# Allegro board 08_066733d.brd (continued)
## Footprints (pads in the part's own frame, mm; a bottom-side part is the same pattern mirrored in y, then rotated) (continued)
DFN2_1_6X1
  rect 0.508x0.787 smd: A(0.604,0) C(-0.604,0)
DFN10_3X3_PAD2_4X1_7
  oval 0.279x0.711 smd: 1(-1,-1.406) 2(-0.5,-1.406) 3(0,-1.406) 4(0.5,-1.406) 5(1,-1.406) 6(1,1.406) 7(0.5,1.406) 8(0,1.406) 9(-0.5,1.406) 10(-1,1.406)
  rect 2.388x1.702 smd: PAD(0,0)
F2606
  rect 1.651x1.651 smd: 1(-3.35,0) 3(3.35,0)
  rect 2.591x2.591 smd: 2(0,0)
L1206
  rect 1.524x1.575 smd: 1(-1.714,0) 2(1.714,0)
L1210H67
  rect 1.245x2.007 smd: 1(-1.272,0) 2(1.272,0)
LED0603-2
  rect 0.787x0.787 smd: A(0.787,0) C(-0.787,0)
LED0603_A
  rect 0.889x0.787 smd: A(0.845,0) C(-0.845,0)
LQFN20_4X3_PAD2_65X1_65
  rect 0.381x0.381 smd: (-1.809,1.31) (-1.809,-1.31) (1.809,1.31) (1.809,-1.31)
  oval 0.279x0.737 smd: 1(-1.25,-1.393) 2(-0.75,-1.393) 3(-0.25,-1.393) 4(0.25,-1.393) 5(0.75,-1.393) 6(1.25,-1.393) 11(1.25,1.393) 12(0.75,1.393) 13(0.25,1.393) 14(-0.25,1.393) 15(-0.75,1.393) 16(-1.25,1.393)
  oval 0.737x0.279 smd: 7(1.893,-0.75) 8(1.893,-0.25) 9(1.893,0.25) 10(1.893,0.75) 17(-1.893,0.75) 18(-1.893,0.25) 19(-1.893,-0.25) 20(-1.893,-0.75)
  rect 2.642x1.651 smd: PAD(0,0)
LSML208W216H122
  rect 1.168x4.394 smd: 1(-1.651,0) 2(1.651,0)
LSMSQ157H83_A
  rect 0.965x3.708 smd: 1(-1.181,0) 2(1.181,0)
LSMSQ157H122
  rect 0.965x3.708 smd: 1(-1.181,0) 2(1.181,0)
POWERFLAT_33X33
  rect 0.406x0.762 smd: 1(-0.975,-1.519) 2(-0.325,-1.519) 3(0.325,-1.519) 4(0.975,-1.519)
  round 0.127 smd: 5(0.975,1.519) 6(0.325,1.519) 7(-0.325,1.519)
  custom 0.597x0.597 smd: 8(-1.029,1.519)
QFN12_2X2_PAD0_7X0_7
  oval 0.279x0.711 smd: 1(-0.75,-0.906) 2(-0.25,-0.906) 3(0.25,-0.906) 4(0.75,-0.906) 7(0.75,0.906) 8(0.25,0.906) 9(-0.25,0.906) 10(-0.75,0.906)
  oval 0.711x0.279 smd: 5(0.906,-0.25) 6(0.906,0.25) 11(-0.906,0.25) 12(-0.906,-0.25)
  rect 0.711x0.711 smd: PAD(0,0)
QFN14_3_5X3_5_PAD2_05X2_05
  oval 0.889x0.305 smd: 1(-1.7,-0.75) 7(1.7,-0.75) 8(1.7,0.75) 14(-1.7,0.75)
  oval 0.305x0.889 smd: 2(-1,-1.7) 3(-0.5,-1.7) 4(0,-1.7) 5(0.5,-1.7) 6(1,-1.7) 9(1,1.7) 10(0.5,1.7) 11(0,1.7) 12(-0.5,1.7) 13(-1,1.7)
  rect 2.057x2.057 smd: PAD(0,0)
QFN18_3X3_PAD1_51X1_7
  oval 0.279x0.711 smd: 1(-1,-1.406) 2(-0.5,-1.406) 3(0,-1.406) 4(0.5,-1.406) 5(1,-1.406) 10(1,1.406) 11(0.5,1.406) 12(0,1.406) 13(-0.5,1.406) 14(-1,1.406)
  oval 0.711x0.279 smd: 6(1.371,-0.75) 7(1.371,-0.25) 8(1.371,0.25) 9(1.371,0.75) 15(-1.371,0.75) 16(-1.371,0.25) 17(-1.371,-0.25) 18(-1.371,-0.75)
  rect 1.499x1.702 smd: PAD(0,0)
QFN24_4X4_PAD2_5X2_5
  oval 0.305x0.991 smd: 1(-1.25,-2) 2(-0.75,-2) 3(-0.25,-2) 4(0.25,-2) 5(0.75,-2) 6(1.25,-2) 13(1.25,2) 14(0.75,2) 15(0.25,2) 16(-0.25,2) 17(-0.75,2) 18(-1.25,2)
  oval 0.991x0.305 smd: 7(2,-1.25) 8(2,-0.75) 9(2,-0.25) 10(2,0.25) 11(2,0.75) 12(2,1.25) 19(-2,1.25) 20(-2,0.75) 21(-2,0.25) 22(-2,-0.25) 23(-2,-0.75) 24(-2,-1.25)
  rect 2.489x2.489 smd: PAD(0,0)
QFN24_4X4_PAD2_7X2_7
  oval 0.305x0.787 smd: 1(-1.25,-2) 2(-0.75,-2) 3(-0.25,-2) 4(0.25,-2) 5(0.75,-2) 6(1.25,-2) 13(1.25,2) 14(0.75,2) 15(0.25,2) 16(-0.25,2) 17(-0.75,2) 18(-1.25,2)
  oval 0.787x0.305 smd: 7(2,-1.25) 8(2,-0.75) 9(2,-0.25) 10(2,0.25) 11(2,0.75) 12(2,1.25) 19(-2,1.25) 20(-2,0.75) 21(-2,0.25) 22(-2,-0.25) 23(-2,-0.75) 24(-2,-1.25)
  rect 2.692x2.692 smd: PAD(0,0)
QFN32_5X5_PAD3_2X3_2
  oval 0.305x0.889 smd: 1(-1.75,-2.45) 2(-1.25,-2.45) 3(-0.75,-2.45) 4(-0.25,-2.45) 5(0.25,-2.45) 6(0.75,-2.45) 7(1.25,-2.45) 8(1.75,-2.45) 17(1.75,2.45) 18(1.25,2.45) 19(0.75,2.45) 20(0.25,2.45) 21(-0.25,2.45) 22(-0.75,2.45) 23(-1.25,2.45) 24(-1.75,2.45)
  oval 0.889x0.305 smd: 9(2.45,-1.75) 10(2.45,-1.25) 11(2.45,-0.75) 12(2.45,-0.25) 13(2.45,0.25) 14(2.45,0.75) 15(2.45,1.25) 16(2.45,1.75) 25(-2.45,1.75) 26(-2.45,1.25) 27(-2.45,0.75) 28(-2.45,0.25) 29(-2.45,-0.25) 30(-2.45,-0.75) 31(-2.45,-1.25) 32(-2.45,-1.75)
  rect 3.2x3.2 smd: PAD(0,0)
R0402
  rect 0.635x0.737 smd: 1(-0.5,0) 2(0.5,0)
R0603
  rect 0.787x0.991 smd: 1(-0.85,0) 2(0.85,0)
R0805
  rect 1.041x1.397 smd: 1(-0.95,0) 2(0.95,0)
R1206
  rect 1.041x1.753 smd: 1(-1.5,0) 2(1.5,0)
RESNET8
  rect 0.533x0.813 smd: 1(-0.89,-0.606) 4(0.89,-0.606) 5(0.89,0.606) 8(-0.89,0.606)
  rect 0.254x0.813 smd: 2(-0.25,-0.606) 3(0.25,-0.606) 6(0.25,0.606) 7(-0.25,0.606)
SC70-5_A
  rect 0.406x0.94 smd: 1(-0.65,-1.1) 2(0,-1.1) 3(0.65,-1.1) 4(0.65,1.1) 5(-0.65,1.1)
SMA
  rect 2.032x2.032 smd: A(1.994,0) C(-1.994,0)
SO16WB
  rect 0.635x1.727 smd: 1(-4.445,-4.801) 2(-3.175,-4.801) 3(-1.905,-4.801) 4(-0.635,-4.801) 5(0.635,-4.801) 6(1.905,-4.801) 7(3.175,-4.801) 8(4.445,-4.801) 9(4.445,4.801) 10(3.175,4.801) 11(1.905,4.801) 12(0.635,4.801) 13(-0.635,4.801) 14(-1.905,4.801) 15(-3.175,4.801) 16(-4.445,4.801)
SOT23-5L-2
  rect 0.61x1.194 smd: 1(-0.95,-1.15) 2(0,-1.15) 3(0.95,-1.15) 4(0.95,1.15) 5(-0.95,1.15)
SOT23_6-3
  rect 0.635x1.067 smd: 1(-0.95,-1.1) 2(0,-1.1) 3(0.95,-1.1) 4(0.95,1.1) 5(0,1.1) 6(-0.95,1.1)
SOT143A
  rect 1.092x1.27 smd: 1(-0.76,-1)
  rect 0.711x1.27 smd: 2(0.96,-1) 3(0.96,1) 4(-0.96,1)
SWSML165W110H75
  rect 0.889x0.991 smd: 1A(-2.044,-0.795) 1B(2.044,-0.795) 2A(-2.044,0.795) 2B(2.044,0.795)
SWSMSQ394H268
  rect 1.194x2.591 smd: 1(-2.54,-5.995) 2(2.54,5.995) 4(2.54,-5.995) 8(-2.54,5.995) C1(0,-5.995) C2(0,5.995)
TSOT-5
  rect 0.508x1.524 smd: 1(-0.95,-1.17) 2(0,-1.17) 3(0.95,-1.17) 4(0.95,1.17) 5(-0.95,1.17)
TSSOP14
  rect 0.432x1.778 smd: 1(-1.95,-2.92) 2(-1.3,-2.92) 3(-0.65,-2.92) 4(0,-2.92) 5(0.65,-2.92) 6(1.3,-2.92) 7(1.95,-2.92) 8(1.95,2.92) 9(1.3,2.92) 10(0.65,2.92) 11(0,2.92) 12(-0.65,2.92) 13(-1.3,2.92) 14(-1.95,2.92)
UDFN10_2_5X1
  oval 0.254x0.508 smd: 1(-1,-0.404) 2(-0.5,-0.404) 4(0.5,-0.404) 5(1,-0.404) 6(1,0.404) 7(0.5,0.404) 9(-0.5,0.404) 10(-1,0.404)
  oval 0.457x0.508 smd: 3(0,-0.404) 8(0,0.404)
unnamed
  round 4.445 hole 3.175 unplated: (0,0)
YSML79W63H31
  rect 0.61x0.787 smd: 1(-0.905,-0.594) 2(0.905,-0.594) 3(0.905,0.594) 4(-0.905,0.594)
YSML98W79H35
  rect 1.092x0.991 smd: 1(-0.921,-0.72) 2(0.921,-0.72) 3(0.921,0.72) 4(-0.921,0.72)
YSML126W98H31
  rect 1.397x1.194 smd: 1(-1.1,-0.95) 2(1.1,-0.95) 3(1.1,0.95) 4(-1.1,0.95)

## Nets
DGND: C1.2(N2) C2.2(N2) C3.2(N2) C4.2(N2) C5.2(N2) C6.2(N2) C7.2(N2) C8.2(N2) C9.2(N2) C10.2(N2) C11.2(N2) C12.2(N2) C13.2(N2) C14.2(N2) C15.2(N2) C16.2(N2) C17.2(N2) C18.2(N2) C19.2(N2) C20.2(N2) C21.2(N2) C22.2(N2) C23.2(N2) C24.2(N2) C25.2(N2) C26.2(N2) C27.2(N2) C28.2(N2) C29.2(N2) C30.2(N2) C31.2(N2) C32.2(N2) C33.2(N2) C34.2(N2) C35.2(N2) C36.2(N2) C37.2(N2) C38.2(N2) C40.2(N2) C41.2(N2) C42.2(N2) C43.2(N2) C44.2(N2) C45.2(N2) C46.2(N2) C48.2(N2) C49.2(N2) C50.2(N2) C51.2(N2) C52.2(N2) C53.2(N2) C54.2(N2) C55.2(N2) C56.2(N2) C57.2(N2) C58.2(N2) C59.2(N2) C60.2(N2) C61.2(N2) C62.2(N2) C63.2(N2) C64.2(N2) C65.2(N2) C66.2(N2) C67.2(N2) C68.2(N2) C69.2(N2) C70.2(N2) C71.2(N2) C72.2(N2) C73.2(N2) C74.2(N2) C75.2(N2) C76.2(N2) C77.2(N2) C78.2(N2) C79.2(N2) C80.2(N2) C81.2(N2) C82.2(N2) C83.2(N2) C84.2(N2) C85.2(N2) C86.2(N2) C87.2(N2) C88.2(N2) C89.2(N2) C90.2(N2) C91.2(N2) C92.2(N2) C93.2(N2) C94.2(N2) C95.2(N2) C96.2(N2) C97.2(N2) C98.2(N2) C99.2(N2) C100.2(N2) C101.2(N2) C102.2(N2) C103.2(N2) C104.2(N2) C105.2(N2) C106.2(N2) C107.2(N2) C108.2(N2) C109.2(N2) C110.2(N2) C111.2(N2) C112.2(N2) C113.2(N2) C114.2(N2) C115.2(N2) C116.2(N2) C117.2(N2) C118.2(N2) C119.2(N2) C120.2(N2) C121.2(N2) C122.2(N2) C123.2(N2) C124.2(N2) C125.2(N2) C126.2(N2) C127.2(N2) C128.2(N2) C129.2(N2) C130.2(N2) C131.2(N2) C132.2(N2) C133.2(N2) C134.2(N2) C135.2(N2) C136.2(N2) C137.2(N2) C138.2(N2) C139.2(N2) C140.2(N2) C141.2(N2) C142.2(N2) C143.2(N2) C144.2(N2) C145.2(N2) C146.2(N2) C147.2(N2) C148.2(N2) C149.2(N2) C150.2(N2) C151.2(N2) C152.2(N2) C153.2(N2) C154.2(N2) C155.2(N2) C156.2(N2) C157.2(N2) C158.2(N2) C159.2(N2) C161.2(N2) C162.2(N2) C163.2(N2) C164.2(N2) C165.2(N2) C166.2(N2) C167.2(N2) C168.2(N2) C169.2(N2) C170.2(N2) C171.2(N2) C172.2(N2) C173.2(N2) C174.2(N2) C175.2(N2) C176.2(N2) C177.2(N2) C178.2(N2) C179.2(N2) C180.2(N2) C181.2(N2) C182.2(N2) C183.2(N2) C184.2(N2) C185.2(N2) C186.2(N2) C187.2(N2) C188.2(N2) C189.2(N2) C190.2(N2) C191.2(N2) C192.2(N2) C193.2(N2) C194.2(N2) C196.2(N2) C197.2(N2) C198.2(N2) C199.2(N2) C200.2(N2) C201.2(N2) C202.2(N2) C203.2(N2) C204.2(N2) C205.2(N2) C206.2(N2) C211.2(N2) C212.2(N2) C213.2(N2) C214.2(N2) C215.2(N2) C216.2(N2) C217.2(N2) C218.2(N2) C219.2(N2) C221.2(N2) C222.2(N2) C223.2(N2) C224.2(N2) C225.2(N2) C226.2(N2) C227.2(N2) C228.2(N2) C229.2(N2) C230.2(N2) C231.2(N2) C232.2(N2) C233.2(N2) C234.2(N2) C235.2(N2) C236.2(N2) C237.2(N2) C238.2(N2) C239.2(N2) C240.2(N2) C241.2(N2) C242.2(N2) C243.2(N2) C244.2(N2) C245.2(N2) C246.2(N2) C247.2(N2) C248.2(N2) C249.2(N2) C250.2(N2) C251.2(N2) C252.2(N2) C253.2(N2) C254.2(N2) D1.2 D1.5 D2.3 D2.8 D15.A(P) D17.2 D18.A(P) FL1.2 FL2.2 J1.1 J1.2 J1.43 J1.44 J1.45 J1.46 J1.55 J1.56 J1.87 J1.94 J2.1 J2.2 J2.24 J2.25 J2.48 J2.51 J2.62 J2.68 J2.71 J2.79 J2.80 J3.1 J3.2 J3.22 J3.25 J3.36 J3.39 J3.41 J3.46 J3.60 J3.76 J3.85 J3.90 J3.98 J3.100 P1.A1 P1.A12 P1.B1 P1.B12 P1.GND1 P1.GND2 P6.3 P6.5 R1.2(N2) R4.2(N2) R6.2(N2) R10.2(N2) R17.2(N2) R24.2(N2) R25.2(N2) R26.2(N2) R31.2(N2) R50.2(N2) R54.2(N2) R56.2(N2) R57.2(N2) R58.2(N2) R65.2(N2) R66.2(N2) R68.2(N2) R77.2(N2) R79.2(N2) R80.2(N2) R82.2(N2) R84.2(N2) R91.2(N2) R93.2(N2) R95.1 R98.2(N2) R103.2(N2) R106.2(N2) R109.2(N2) R113.2(N2) R115.2(N2) R117.2(N2) R125.2(N2) R126.2(N2) R127.2(N2) S2.1A S2.1B U1.A1 U1.A20 U1.B2 U1.B19 U1.C3 U1.C18 U1.D4 U1.D17 U1.E5(GND_9) U1.E9 U1.E13 U1.E16 U1.F6 U1.F15 U1.G1 U1.G7 U1.G8 U1.G9 U1.G10 U1.G11 U1.G15 U1.H1 U1.J6 U1.J7 U1.J8 U1.J9 U1.J10 U1.J11 U1.J12 U1.J13 U1.J14 U1.J15 U1.K1 U1.L6 U1.L7 U1.L8 U1.L9 U1.L10 U1.L11 U1.L12 U1.L13 U1.L14 U1.L15 U1.M1 U1.M20 U1.N8 U1.N9 U1.N10 U1.N11 U1.N12 U1.N13 U1.P1 U1.P7 U1.P8 U1.P9 U1.P13 U1.P14 U1.R6 U1.R15 U1.T1 U1.T5 U1.T8 U1.T16 U1.U4 U1.U17 U1.V3 U1.V18 U1.W2 U1.W19 U1.Y1 U1.Y20 U2.3 U2.8 U2.PAD U3.3 U3.4 U3.6 U3.23 U3.PAD U4.10 U5.3 U6.3 U6.10 U6.22(VSYS) U6.PAD U7.7 U8.A9 U8.B1 U8.B3 U8.B9 U8.D1 U8.D8 U8.E1 U8.E2 U8.E8 U8.F9 U8.G1 U8.G8 U8.G9 U8.J2 U8.J8 U8.M1 U8.M9 U8.P1 U8.P9 U8.T1 U8.T9 U9.3 U10.3 U11.3 U12.7 U12.PAD U13.3 U14.1 U15.4 U15.17 U15.20 U15.24 U15.26 U15.PAD U16.2 U16.5 U16.10 U16.PAD U17.1 U17.4 U17.7 U17.PAD U18.2 U19.A6 U19.C4 U19.E7 U19.G5 U19.H10 U19.J5 U19.K8(VSS_6) U19.N2 U19.N5 U19.P4 U19.P6 U20.7 U20.PAD U21.7 U21.PAD U22.7 U22.PAD U23.7 U23.PAD U24.23(VSS) U24.PAD U25.7 U25.PAD U26.2 U26.5(WP) VR1.4 VR1.13 VR1.PAD Y1.2 Y1.4 Y2.2 Y2.4 Y3.2 Y3.4 Y4.2 Y5.2 Y6.2
VDD_CONNECTOR: J3.97 J3.99 JP1.3(N3)
VDD_DMC: C1.1 C2.1 C3.1 C5.1 C6.1 C7.1 C8.1 C11.1 C13.1 C39.1 C48.1 C53.1 C58.1 C63.1 C69.1 C74.1 C79.1 C84.1 C89.1 C94.1 C98.1 C102.1 C106.1 C110.1 C114.1 C118.1 C122.1 C126.1 C130.1 C134.1 C138.1 C142.1 C146.1 C150.1 C153.1 C156.1 C162.1 C220.1 C224.1 C227.1 C230.1 J3.92 L4.2(N2) R8.1 R9.1 R108.1 TP3.1(N1) U1.E10 U1.E11 U1.E12 U1.F7 U1.F8 U1.F9 U1.F10 U1.F11 U1.F12 U1.F13 U1.F14 U2.4 U8.A1 U8.A8 U8.B2 U8.C1 U8.C9 U8.D2 U8.D9 U8.E9 U8.F1 U8.G7 U8.H2 U8.H9 U8.K2 U8.K8 U8.N1 U8.N9 U8.R1 U8.R9
VDD_EXT: C38.1 C49.1 C54.1 C59.1 C64.1 C70.1 C75.1 C80.1 C85.1 C90.1 C95.1 C99.1 C103.1 C107.1 C111.1 C115.1 C119.1 C123.1 C127.1 C131.1 C135.1 C139.1 C143.1 C147.1 C151.1 C154.1 C157.1 C163.1 C173.1 C174.1 C175.1 C176.1 C179.1 C180.1 C181.1 C182.1 C189.1 C191.1 C192.1 C194.1 C197.1 C210.1 C213.1 C215.1 C216.1 C218.1 C219.1 C222.1 C225.1 C228.1 C233.1 C234.1 C235.1 C236.1 C237.1 C238.1 C239.1 C240.1 C241.1 C247.1 C248.1 C249.1 C250.1 C251.1 C252.1 C253.1 C254.1 DS1.A(P) DS2.A(P) DS3.A(P) DS4.A(P) DS5.A(P) DS6.A(P) DS7.A(P) DS8.A(P) L3.2(N2) P6.1 R5.1 R14.1 R15.1 R29.1 R30.1 R38.1 R41.1 R45.1 R46.1 R47.1 R48.1 R51.1 R53.1 R55.1 R60.1 R61.1 R62.1 R63.1 R64.1 R70.1 R71.1 R75.1 R78.1 R81.1 R83.1 R86.1 R87.1 R104.2(N2) R105.1 R114.1 R116.1 R118.1 R119.1 R120.1 R121.1 R122.1 R131.1 R132.1 R133.1 R134.1 R135.1 R136.1 R137.1 R138.1 R139.1 R140.1 R143.1 S1.C1 S1.C2 TP1.1(N1) U1.H7 U1.H9 U1.H11 U1.H13 U1.H14 U1.K7 U1.K14 U1.M7 U1.M14 U1.N7 U1.N14 U2.2 U2.7 U2.10 U4.2 U5.5(VCC) U7.14(VCC) U9.5(VCC) U10.5(VCC) U11.5 U12.14(VCC) U13.5 U14.4(VCC) U16.3 U16.4 U16.11 U16.12(VIN_4) U16.13 U16.15 U17.3 U17.8(VIN_2) U17.10 U18.1 U18.3 U19.C6 U19.E6 U19.F5 U19.J10 U19.K9 U19.M4 U19.N4 U19.P3 U19.P5 U20.14(VCC) U21.14(VCC) U22.14(VCC) U23.14(VCC) U24.8 U25.14(VCC) U26.4 VR1.2 Y4.4(VCC) Y5.4(VDD) Y6.4(VDD)
VDD_INPUT: C190.1 C196.1 C198.1 C203.1 C205.1 JP1.2 R96.1 VR1.6 VR1.11(VIN_2)
VDD_INT: C50.1 C51.1 C55.1 C56.1 C60.1 C61.1 C65.1 C66.1 C68.1 C71.1 C73.1 C76.1 C78.1 C81.1 C83.1 C86.1 C88.1 C91.1 C93.1 C96.1 C100.1 C104.1 C108.1 C112.1 C116.1 C120.1 C124.1 C128.1 C132.1 C136.1 C140.1 C144.1 C148.1 C152.1 C155.1 C161.1 C164.1 C165.1 C208.1 C209.2(N2) C211.1 C212.1 C214.1 C217.1 C221.1 C223.1 C226.1 C229.1 L1.1 L2.2(N2) R44.1 R99.2(N2) R101.1 R107.2(N2) TP2.1(N1) U1.G6 U1.G12 U1.G13 U1.G14 U1.H6 U1.H8 U1.H10 U1.H12 U1.H15 U1.K6 U1.K10 U1.K11 U1.K12 U1.K13 U1.K15 U1.M6 U1.M10 U1.M11 U1.M12 U1.M13 U1.M15 U1.N6 U1.N15 U1.P6 U1.P15 U1.R7 U1.R8 U1.R9 U1.R10 U1.R11 U1.R12 U1.R13 U1.R14 U1.T6 U1.T7 U1.T14 U1.T15 U1.U7 U1.U15
VDD_PLL: C46.1 C47.1 C242.1 C243.1 C244.1 L1.2(N2) U1.K8 U1.K9 U1.M8 U1.M9
VDD_REF: C52.1 C57.1 C62.1 C67.1 C72.1 C77.1 C82.1 C87.1 C92.1 C97.1 C101.1 C105.1 C109.1 C113.1 C117.1 C121.1 C125.1 C129.1 C133.1 C137.1 C141.1 C145.1 C149.1 C231.1 FL2.1 R16.1 R32.1 R33.1 R39.1 R42.1 R43.1 TP4.1(N1) U1.P10 U1.P11 U1.P12 U18.5(VOUT)
AUDIO_CLK: J3.40 R36.2(N2) R141.2(N2)
CLK1: J3.42 R35.2(N2) R142.2(N2)
CLK2: J3.44 R37.2(N2) R144.2(N2)
CON_RESET_IN*: J3.96 R62.2(N2) U11.2
DAI0_PIN01: J1.3 U1.U13
DAI0_PIN02: J1.5 U1.W15
DAI0_PIN03: J1.7 U1.Y16
DAI0_PIN04: J1.9 U1.W13
DAI0_PIN05: J1.11 U1.V15
DAI0_PIN06: J1.13 U1.Y17
DAI0_PIN07: J1.15 U1.W16
DAI0_PIN08: J1.17 U1.V14
DAI0_PIN09: J1.19 U1.T13
DAI0_PIN10: J1.21 U1.U14
DAI0_PIN11: J1.23 U1.V16
DAI0_PIN12: J1.25 U1.Y18
DAI0_PIN13: J1.27 U1.N16
DAI0_PIN14: J1.29 U1.R17
DAI0_PIN15: J1.31 U1.P17
DAI0_PIN16: J1.33 U1.T18
DAI0_PIN17: J1.35 U1.R18
DAI0_PIN18: J1.37 U1.U19
DAI0_PIN19: J1.39 U1.Y19
DAI0_PIN20: J1.41 U1.W18
DAI1_PIN01: J1.4 U1.L16
DAI1_PIN02: J1.6 U1.J20
DAI1_PIN03: J1.8 U1.K18
DAI1_PIN04: J1.10 U1.L17
DAI1_PIN05: J1.12 U1.L18
DAI1_PIN06: J1.14 U1.M18
DAI1_PIN07: J1.16 U1.N18
DAI1_PIN08: J1.18(N9) U1.P18
DAI1_PIN09: J1.20 U1.M17
DAI1_PIN10: J1.22 U1.M16
DAI1_PIN11: J1.24 U1.N17
DAI1_PIN12: J1.26 U1.T19
DAI1_PIN13: J1.28 U1.J19
DAI1_PIN14: J1.30 U1.H20
DAI1_PIN15: J1.32 U1.K17
DAI1_PIN16: J1.34 U1.J18
DAI1_PIN17: J1.36 U1.H19
DAI1_PIN18: J1.38 U1.G20
DAI1_PIN19: J1.40 U1.T20
DAI1_PIN20: J1.42 U1.U20
DMC0_A00: RN1.1 U1.C15 U8.N3
DMC0_A01: RN3.2 U1.A16 U8.P7
DMC0_A02: RN2.2 U1.E14 U8.P3
DMC0_A03: RN5.2 U1.A15 U8.N2
DMC0_A04: RN4.1 U1.C14 U8.P8
DMC0_A05: RN5.3 U1.D15 U8.P2
DMC0_A06: RN3.4 U1.B14 U8.R8
DMC0_A07: RN5.4 U1.B15 U8.R2
DMC0_A08: RN3.3 U1.A14 U8.T8
DMC0_A09: RN2.4 U1.C13 U8.R3
DMC0_A10: RN7.1 U1.C11 U8.L7
DMC0_A11: RN1.4 U1.B13 U8.R7
DMC0_A12: RN4.2 U1.B11 U8.N7
DMC0_A13: RN2.3 U1.A13 U8.T3
DMC0_A14: RN3.1 U1.C10 U8.T7
DMC0_A15: RN4.4 U1.C12 U8.M7
DMC0_BA0: RN5.1 U1.D13 U8.M2
DMC0_BA1: RN4.3 U1.D14 U8.N8
DMC0_BA2: RN1.2 U1.E15 U8.M3
DMC0_CAS*: RN6.3 U1.C17 U8.K3
DMC0_CK: R3.1 U1.A17 U8.J7
DMC0_CK*: R3.2(N2) U1.A18 U8.K7
DMC0_CKE: RN7.2 U1.B17 U8.K9
DMC0_CS0*: RN6.4 U1.C16 U8.L2
DMC0_DQ00: U1.A5 U8.E3
DMC0_DQ01: U1.C7 U8.F7
DMC0_DQ02: U1.D7 U8.F2
DMC0_DQ03: U1.B7 U8.F8
DMC0_DQ04: U1.B6 U8.H3
DMC0_DQ05: U1.B8 U8.H8
DMC0_DQ06: U1.C6 U8.G2
DMC0_DQ07: U1.C8 U8.H7
DMC0_DQ08: U1.A8 U8.D7
DMC0_DQ09: U1.D9 U8.C3
DMC0_DQ10: U1.B12 U8.C8
DMC0_DQ11: U1.B10 U8.C2
DMC0_DQ12: U1.C9 U8.A7
DMC0_DQ13: U1.A12 U8.A2
DMC0_DQ14: U1.D8 U8.B8
DMC0_DQ15: U1.B9 U8.A3
DMC0_LDM: U1.E8 U8.E7
DMC0_LDQS: U1.A6 U8.F3
DMC0_LDQS*: U1.A7 U8.G3
DMC0_ODT: RN6.2 U1.B18 U8.K1
DMC0_RAS*: RN6.1 U1.D16 U8.J3
DMC0_RESET*: R8.2(N2) RN2.1 U1.D10 U8.T2
DMC0_RZQ: R1.1 U1.B16
DMC0_UDM: U1.D12 U8.D3
DMC0_UDQS: U1.A9 U8.C7
DMC0_UDQS*: U1.A10 U8.B7
DMC0_VREF: C4.1 R2.1 R7.2(N2) R11.2(N2)
DMC0_WE*: RN1.3 U1.D11 U8.L3
EMMC_CLK: R110.1 R138.2(N2) U23.8
EMMC_CMD: R118.2(N2) U12.3 U19.M5
EMMC_DAT0: R120.2(N2) U12.8 U19.A3
EMMC_DAT1: R121.2(N2) U12.11 U19.A4
EMMC_DAT2: R122.2(N2) U19.A5 U21.3
EMMC_DAT3: R131.2(N2) U19.B2 U21.6
EMMC_DAT4: R132.2(N2) U19.B3 U21.8
EMMC_DAT5: R133.2(N2) U19.B4 U21.11
EMMC_DAT6: R134.2(N2) U19.B5 U23.3
EMMC_DAT7: R135.2(N2) U19.B6 U23.6
EMMC_EN*: R114.2(N2) R115.1 U12.1 U12.4 U12.10 U12.13 U21.1 U21.4 U21.10 U21.13 U23.1 U23.4 U23.10 U23.13 U24.24
EMMC_SOM_EN*: R116.2(N2) R117.1 U20.1 U20.4 U20.10 U20.13 U22.1 U22.4 U22.10 U22.13 U24.1 U25.1 U25.4 U25.10 U25.13
HADC0_VIN0: J1.47 U1.K20
HADC0_VIN1: J1.49 U1.L20
HADC0_VIN2: J1.51 U1.K19
HADC0_VIN3: J1.53 U1.L19
HADC0_VIN4: J1.48 U1.P19
HADC0_VIN5: J1.50 U1.P20
HADC0_VIN6: J1.52 U1.M19
HADC0_VIN7: J1.54 U1.N19
ID0: J2.76 R136.2(N2) U26.1
ID1: J2.78 R137.2(N2) U26.3
INTVCC: C206.1 R94.2(N2) R100.2(N2) VR1.3
JTG0_TCK/SWCLK: J3.50 P6.4 U1.B4
JTG0_TD0/SW0: J3.52 P6.6 U1.A3
JTG0_TDI: J3.54 P6.8 U1.A4
JTG0_TMS/SWDIO: J3.48 P6.2 U1.B5
JTG0_TRST*: J3.56 P6.9 R78.2(N2) R79.1 U1.C5
LTC3310_EN: R92.2(N2) U16.1
MLB0_CLKN: J1.91 U1.Y8
MLB0_CLKP: J1.89 U1.Y9
MLB0_DATN: J1.99 U1.Y10
MLB0_DATP: J1.97 U1.Y11
MLB0_SIGN: J1.95 U1.Y12
MLB0_SIGP: J1.93 U1.Y13
PA_00/SPI2_MISO/OSPI_MISO/SMC0_D00: J2.3 R52.2(N2) U1.K2
PA_01/SPI2_MOSI/OSPI_MOSI/SMC0_D01: J2.5 U1.L3 U4.15
PA_02/SPI2_D2/OSPI_D2/TWI3_SCL/SMC0_D02/TM0_ACLK3: J2.7 U1.L2 U10.2
PA_03/SPI2_D3/OSPI_D3/TWI3_SDA/SMC0_D03: J2.9 U1.L5 U5.2
PA_04/SPI2_CLK/OSPI_CLK/SMC0_D04: J2.11 R49.1 U1.L4
PA_05/SPI2_SEL1B/OSPI_SEL1B/SMC0_D05/SPI2_SSB: J2.13 U1.M2 U9.2
PA_06/SPI0_CLK/UART0_TXB/OSPI_D4/SMC0_D06/TM0_ACLK1: J2.4 J2.15 U1.M3 U7.9
PA_07/SPI0_MISO/UART0_RXB/OSPI_D5/SMC0_D07/TM0_ACI0: J2.6 J2.17 U1.N2 U7.12
PA_08/SPI0_MOSI/UART0_RTSB/OSPI_D6/SMC0_D08/TM0_ACLK2: J2.8 J2.19 U1.P2 U7.2
PA_09/SPI0_SEL1B/UART0_CTSB/OSPI_D7/SMC0_D09/SPI0_SSB: J2.10 J2.21 U1.N3 U7.5
PA_10/TWI0_SCL/SPI1_CLK/TM0_TMR0/SMC0_D10: J2.14 J2.31 U1.M5
PA_11/TWI0_SDA/SPI1_MISO/HADC0_EOC_OUT/SMC0_D11/TM0_ACI4: J2.16 J2.33 U1.V7
PA_12/FLG0/SPI1_MOSI/TM0_TMR1/SMC0_D12: J2.18(N9) U1.U8
PA_13/FLG1/SPI1_SEL1B/TM0_TMR2/SMC0_D13/SPI1_SSB: J2.20 U1.Y5
PA_14/TWI2_SCL/SPI1_D2/UART1_RXB/SMC0_D14/TM0_ACI1: R13.1 U1.V6
PA_15/TWI2_SDA/SPI1_D3/UART1_TXB/SMC0_D15: R12.1 U1.T9
PB_00/MLB0_DAT/TWI1_SCL/UART1_RTSB/SMC0_AMS0B/TM0_ACI3: J1.100 J2.35 U1.A19
PB_01/MLB0_SIG/TWI1_SDA/UART1_CTSB/SMC0_AREB/TM0_CLK: J1.98 J2.37 U1.E17
PB_02/MLB0_CLK/FLG3/LP1_ACK/SMC0_AWEB/TM0_ACLK4: J1.96 J2.98 U1.F16
PB_03/TM0_TMR3/FLG2/SPI2_SEL2B/SMC0_ADDR1/CNT0_UD: J1.88 J2.23 U1.D5
PB_04/TM0_TMR4/SPI1_RDY/LP0_ACK/SMC0_ADDR2/CNT0_ZM: J1.90 J2.28 J2.97 R111.1 U1.E6
PB_05/TM0_TMR5/SPI2_RDY/SPI0_SEL2B/SMC0_ADDR3/CNT0_DG: J1.92 J2.12 R112.2(N2) U1.C4
PB_06/LP0_CLK/SPI1_SEL5B/TRACE0_CLK: J2.99 U1.V4
PB_07/LP0_D0/SPI2_SEL5B/TRACE0_D00: J2.95 U1.Y3
PB_08/LP0_D1/SPI1_SEL7B/TM0_TMR6/TRACE0_D01: J2.93 U1.Y2
PB_09/LP0_D2/SPI2_SEL7B/TM0_TMR7/TRACE0_D02: J2.91 U1.Y4
PB_10/LP0_D3/SPI1_SEL2B/TRACE0_D03: J2.22 J2.89 U1.U5
PB_11/LP0_D4/SPI0_RDY/UART2_RXB/TM0_ACI2: J2.87 U1.U6
PB_12/LP0_D5/SPI2_SEL3B/UART2_TXB: J2.85 U1.V5
PB_13/LP0_D6/SPI1_SEL3B/UART2_RTSB: J2.83 U1.W5
PB_14/LP0_D7/SPI0_SEL3B/UART2_CTSB: J2.81 U1.W17
PB_15/LP1_D0/SPI0_SEL4B/MIS0_CD/SMC0_ADDR4: J2.60 J2.96 U20.6
PB_15/LP1_D0/SPI0_SEL4B/MIS0_CD/SMC0_ADDR4_Z: U1.V20 U12.5 U20.5
PC_00/LP1_D1/TWI4_SCL/TRACE0_D04/SPI1_SEL4B: J2.94 U1.W20
PC_01/LP1_D2/TWI4_SDA/TRACE0_D05/SPI2_SEL4B: J2.92 U1.V19
PC_02/LP1_D3/TWI5_SCL/TRACE0_D06/SPI1_SEL6B: J2.90 U1.V17
PC_03/LP1_D4/TWI5_SDA/TRACE0_D07/SPI2_SEL6B: J2.88 U1.U16
PC_04/LP1_D5/OSPI_SEL2B/SMC0_ADDR5: J2.86 U1.U18
PC_05/LP1_D6/OSPI_SEL3B/TM0_TMR8/SMC0_ADDR6: J2.84 U1.P16
PC_06/LP1_D7/SPI1_RDY/MSI0_WP/SMC0_ADDR7: J2.82 U1.R16
PC_07/LP1_CLK/OSPI_SEL4B/TM0_TMR9/SYS_FAULT: J2.100 U1.T17
PC_08/OSPI0_CLK/PPI0_D16: J3.83 U1.M4
PC_09/OSPI0_D3/PPI0_D17: J3.62 U1.R2
PC_10/OSPI0_D2/PPI0_D18: J3.64 U1.U1
PC_11/OSPI0_MOSI/PPI0_D19: J3.66 U1.N4
PC_12/OSPI0_MISO/PPI0_D20: J3.68 U1.P3
PC_13/OSPI0_D7/PPI0_D21: J3.70 U1.T2
PC_14/OSPI0_D6/PPI0_D22: J1.85 J3.72 U1.V1
PC_15/OSPI0_D5/PPI0_D23: J1.86 J3.74 U1.N5
PD_00/OSPI0_D4: J2.50 U1.U2
PD_01/OSPI0_SELB/PPI0_D06: J3.63 U1.R3
PD_02/UART1_RTSB/SH1_FLG10/ETH0_CRS: J2.36 U1.P4
PD_03/UART1_CTSB/SH0_FLG11/LP0_ACK/ETH0_PTPAUXIN2: J2.38 U1.T3
PD_04/UART1_RXB/OSPI0_DQS/PPI0_D07/TM0_ACI1: J2.27 J2.34 J3.65 U1.V2
PD_05/UART1_TXB/PPI0_D08/ETH0_PTPAUXIN1: J2.32 J3.67 U1.W1
PD_06/UART0_CTSB/ETH0_RX_ER: J2.49 U1.U3
PD_07/UART0_RTSB/ETH0_COL: J2.47 U1.T4
PD_08/UART0_RXB/TM0_ACI0: J2.45 U1.R5
PD_09/UART0_TXB: J2.43 U1.P5
PD_10/UART2_RXB/PPI0_D09/TM0_ACI2: J2.42 J3.69 U1.R4
PD_11/UART2_TXB/PPI0_D10: J2.40 J3.71 U1.W3
PD_12/ETH0_PHY_INT/TM0_TMR6/UART2_RTSB/PPI0_D11: J2.44 J3.7 J3.73 U1.W4
PD_13/TM0_TMR7/UART2_CTSB/PPI0_D12: J2.46 J3.75 U1.Y7
PD_14/TWI4_SCL/LP1_ACK/SH1_FLG9/PPI0_D13: J3.77 U1.W6
PD_15/TWI4_SDA/MSI0_D0/TM0_TMR15/PPI0_D14: J2.55 J3.79 U20.8
PD_15/TWI4_SDA/MSI0_D0/TM0_TMR15/PPI0_D14_Z: U1.Y6 U12.9 U20.9
PE_00/TWI5_SCL/SPI3_SEL3B/PPI0_D15: J3.81 U1.W7
PE_01/TWI5_SDA/MSI0_D1/SPI3_SEL4B/PPI0_FS1/TM0_ACLK15: J2.57 J3.45 U20.11
PE_01/TWI5_SDA/MSI0_D1/SPI3_SEL4B/PPI0_FS1/TM0_ACLK15_Z: U1.U9 U12.12 U20.12
PE_02/TWI0_SCL/SPI1_SEL4B/HADC0_MUX0/PPI0_FS2: J3.47 U1.V8
PE_03/TWI0_SDA/SPI2_SEL3B/HADC0_MUX2/PPI0_FS3/TM0_ACLK4: J3.49 U1.W8
PE_04/TWI2_SCL/HADC0_MUX1/PPI0_CLK: J3.43 U1.W9
PE_05/TWI2_SDA/PPI0_D00: J3.51 U1.V10
PE_06/TM0_TMR8/SH0_FLG2/MSI0_D2/PPI0_D01: J2.59 J3.53 U22.3
PE_06/TM0_TMR8/SH0_FLG2/MSI0_D2/PPI0_D01_Z: U1.U10 U21.2 U22.2
PE_07/TM0_TMR9/SH0_FLG3/SPI1_RDY/PPI0_D02: J3.55 U1.W12
PE_08/TM0_TMR0/MSI0_D3/PPI0_D03: J2.61 J3.57 U22.6
PE_08/TM0_TMR0/MSI0_D3/PPI0_D03_Z: U1.V9 U21.5 U22.5
PE_09/TM0_TMR1/MSI0_CLK/PPI0_D04/ETH0_PTPAUXIN3: J2.56 J3.59 U25.8
PE_09/TM0_TMR1/MSI0_CLK/PPI0_D04/ETH0_PTPAUXIN3_Z: U1.W10 U23.9 U25.9
PE_10/TM0_TMR2/SPI0_SEL4B/PPI0_D05: J3.61 U1.F20
PE_11/ETH1_REFCLK/SH1_FLG7: J3.78 U1.G19
PE_12/ETH1_TXEN/SH0_FLG8: J3.12 U1.H18
PE_13/ETH1_TXD0/SH1_FLG13: J3.14 U1.J17
PE_14/ETH1_TXD1/SPI2_SEL7B: J3.16 U1.K16
PE_15/ETH1_RXD0/SPI0_SEL6B: J3.10 U1.G18
PF_00/ETH1_RXD1/SPI3_RDY/SPI0_SEL7B: J3.8 U1.F19
PF_01/ETH1_MDIO/SH0_FLG7: J3.4 U1.F18
PF_02/ETH1_MDC/SH0_FLG6: J3.6 U1.E20
PF_03/ETH1_CRS/SH0_FLG10/USB0_STP: J1.76 J3.18(N9) U1.E19
PF_04/USB0_D7/TM0_ACLK13: J1.72 U1.H17
PF_05/MLB0_CLKOUT/USB0_D6/TM0_CLK: J1.70 U1.J16
PF_06/SH1_FLG2/SPI1_SEL7B/USB0_D5: J1.68 U1.G17
PF_07/SH1_FLG3/SPI3_SEL2B/USB0_D4: J1.66 U1.D20
PF_08/SPI3_SEL6B/SH1_FLG8/USB0_NXT/TM0_TMR11: J1.74 U1.D19
PF_09/SH0_FLG9/USB0_DIR: J1.78 U1.C20
PF_10/SH1_FLG4/USB0_D3: J1.64 U1.E18
PF_11/SH1_FLG5/USB0_D2: J1.62 U1.F17
PF_12/SH0_FLG13/USB0_D1: J1.60 U1.H16
PF_13/SH0_FLG12/USB0_D0: J1.58 U1.B20
PF_14/SH1_FLG12/USB0_CLK: J1.80 U1.C19
PF_15/CAN0_RX/TM0_ACI4: J2.66 U1.T10
PG1: R100.1 U17.2 VR1.1
PG2: R92.1 R104.1 U17.11
PG_00/CAN0_TX/TM0_ACLK10: J2.64 U1.U11
PG_01/CAN1_RX/SPI2_SEL6B/MSI0_CMD/TM0_ACI11: J2.58 J2.72 U20.3
PG_01/CAN1_RX/SPI2_SEL6B/MSI0_CMD/TM0_ACI11_Z: U1.W11 U12.2 U20.2
PG_02/CAN1_TX/SPI0_SEL5B/MSI0_D4: J2.63 J2.70 U22.8
PG_02/CAN1_TX/SPI0_SEL5B/MSI0_D4_Z: U1.V11 U21.9 U22.9
PG_03/UART3_TXB: J3.80 U1.Y14
PG_04/UART3_RXB/TM0_ACI13: J3.82 U1.V13
PG_05/SPI3_CLK/TM0_ACLK11: J1.77 U1.W14
PG_06/SPI3_MISO: J1.79 U1.T11
PG_07/SPI3_MOSI/TM0_ACLK12: J1.81 U1.U12
PG_08/SPI3_SEL1B/MSI0_D5/SPI3_SSB: J1.83 J2.65 U22.11
PG_08/SPI3_SEL1B/MSI0_D5/SPI3_SSB_Z: U1.Y15 U21.12 U22.12
PG_09/UART3_RTSB/SPI1_SEL6B/SH0_FLG14/MSI0_D6/TM0_ACLK1: J2.67 J3.84 U25.3
PG_09/UART3_RTSB/SPI1_SEL6B/SH0_FLG14/MSI0_D6/TM0_ACLK1_Z: U1.V12 U23.2 U25.2
PG_10/UART3_CTSB/MSI0_D7/SH1_FLG14/TM0_ACLK3: J2.69 J3.86 U25.6
PG_10/UART3_CTSB/MSI0_D7/SH1_FLG14/TM0_ACLK3_Z: U1.T12 U23.5 U25.5
PG_11/SH1_FLG15: J1.82 U1.B3
PG_12/TM0_TMR3/SPI2_SEL4B/SH1_FLG11/OSPI0_SEL3B: J2.54 U1.A2
PG_13/SH0_FLG0/SH1_FLG6/OSPI0_SEL4B: J3.9 U1.B1
PG_14/TM0_TMR10/SPI0_SEL2B/SMC0_ADDR25/TM0_ACI10: J3.11 U1.C2
PG_15/TM0_TMR11/SPI2_RDY/SPI3_SEL5B/SMC0_ADDR24: J2.30 U1.D3
PH_00/TM0_TMR12/SPI3_SEL7B/SMC0_ADDR23/TM0_ACI12: J2.52 U1.E4
PH_01/TM0_TMR13/SPI0_RDY/SMC0_ADDR22/TM0_ACI13: J2.26 U1.F5
PH_02/SH0_FLG1/SPI2_SELB/TM0_TMR14/SMC0_ADDR21: J3.20 U1.G5
PH_03/ETH0_MDC/TRACE0_D08/SMC0_AMS1B: J3.5 U1.K3
PH_04/ETH0_MDIO/TRACE0_D09/SMC0_AMS2B: J3.3 U1.F2
PH_05/ETH0_RXD0/TRACE0_D10/SMC0_AMS3B: J3.19 U1.H2
PH_06/ETH0_RXD1/TRACE0_D11/SMC0_ABE0B: J3.17 U1.K4
PH_07/ETH0_RXCLK_REFLCK/TRACE0_D12/SMC0_ABE1B: J3.21 U1.K5
PH_08/ETH0_RXCTL_RXDV/TRACE0_D13/SMC0_AOEB: J3.23 U1.F1
PH_09/ETH0_TXD0/TRACE0_D14/SMC0_ARDYB: J3.33 U1.H3
PH_10/ETH0_TXD1/TRACE0_D15/SMC0_ADDR8: J3.31 U1.G3
PH_11/ETH0_RXD2/SMC0_ADDR9: J3.15 U1.F3
PH_12/ETH0_RXD3/SMC0_ADDR10: J3.13 U1.J3
PH_13/ETH0_TXCTL_TXEN/SMC0_ADDR11: J3.37 U1.J4
PH_14/ETH0_TXCLK/SMC0_ADD12: J3.35 U1.H4
PH_15/ETH0_TXD2/SMC0_ADDR13: J3.29 U1.G4
PI_00/ETH0_TXD3/SMC0_A14: J3.27 U1.J5
PI_01/SH1_FLG0/ETH0_PTPCLKIN0/TWI2_SCL/SMC0_ADDR15: J3.24 U1.D1
PI_02/SH1_FLG1/ETH0_PTPAUXIN0/TWI3_SDA/SMC0_ADDR16: J3.26 U1.F4
PI_03/TWI1_SCL/SH0_FLG4/ETH0_PTPPPS1/SMC0_ADDR17: J3.30 U1.E3
PI_04/TWI1_SDA/SH0_FLG5/ETH0_PTPPPS0/SMC0_ADDR18: J3.28 U1.D2
PI_05/ETH0_PTPPPS2/OSPI0_SEL2B/SHO_FLG15/SMC0_ADDR19/TM0_ACLK2: J3.32 U1.C1
PI_06/ETH0_PTPPPS3/SMC0_ADDR20/TM0_ACLK14: J3.34 U1.H5
SPI2D2_D3_EN*: R53.2(N2) R54.1 U5.1 U10.1 U24.19
SPI2IFLASH_CS_EN*: R55.2(N2) R56.1 U9.1 U24.18
SPIFLASH_CS*: R46.2(N2) U4.7 U9.4
SPIFLASH_SPI2D2: R48.2(N2) U4.9(WP_N/IO2) U10.4
SPIFLASH_SPI2D3: R47.2(N2) U4.1 U5.4
STUSB_ALERT: R112.1 U6.19
STUSB_RESETB: R111.2(N2) R127.1 U6.6
SYS_BMODE0: R24.1 S1.1 U1.L1
SYS_BMODE1: R25.1 S1.2 U1.G2
SYS_BMODE2: R26.1 S1.4 U1.N1
SYS_CLKIN0: R27.2(N2) R34.2(N2) U1.J1
SYS_CLKIN1: R28.2(N2) R40.2(N2) U1.E2
SYS_CLKOUT: J3.38 U1.J2
SYS_FAULT: R113.1 U1.D18
SYS_FAULT*: J3.88 R59.2(N2) R60.2(N2) U1.G16
SYS_HWRST*: J3.94 R57.1 R73.2(N2) R75.2(N2) U1.D6 U4.3 U14.2 U19.K5 U24.12
SYS_RESOUT*: R61.2(N2) U1.E7
SYS_XTAL0: R18.1 U1.R1
SYS_XTAL1: R19.1 U1.E1
TARGET_RESET*: J3.58 R63.2(N2) R85.2(N2) U11.1
TWI2_SCL: J2.39 R13.2(N2) R15.2(N2) U3.12 U6.7 U24.9
TWI2_SDA: J2.41 R12.2(N2) R14.2(N2) U3.19 U6.8 U24.10
UART0_EN*: R81.2(N2) R82.1 U7.10 U7.13 U24.20
UART0_FLOW_EN*: R83.2(N2) R84.1 U7.1 U7.4 U24.21
UNNAMED_2_ADSPSC59X_I55_DMC0VREF0: R2.2(N2) U1.A11
UNNAMED_2_CAP_I43_N1: C28.1 C30.1 C32.1 C34.1 C39.2(N2) C40.1 R9.2(N2) R10.1 R11.1 U8.H1 U8.M8
UNNAMED_2_CAP_I107_N1: C27.1 C36.1 R7.1 U2.1
UNNAMED_2_ICIS4XTR16256_I54_ZQ: R4.1 U8.L8(ZQ)
UNNAMED_4_CAP_I12_N2: C47.2(N2) R17.1
UNNAMED_4_CAP_I23_N1: C44.1 C45.1 FL1.3(OUT) U1.R20
UNNAMED_4_FLTR3P_I22_IN: FL1.1 R16.2(N2)
UNNAMED_6_CAP_I1_N1: C166.1 R20.2(N2) Y1.1
UNNAMED_6_CAP_I3_N1: C168.1 R22.2(N2) R27.1 Y1.3(IN/OUT2)
UNNAMED_6_CAP_I19_N1: C170.1 R29.2(N2) R32.2(N2) U3.7 U3.24
UNNAMED_6_CAP_I28_N1: C171.1 R33.2(N2) U3.16 U3.20
UNNAMED_6_CAP_I32_N1: C172.1 R38.2(N2) R39.2(N2) U3.11 U3.15
UNNAMED_6_CAP_I37_N1: C167.1 R21.2(N2) Y2.1
UNNAMED_6_CAP_I39_N1: C169.1 R23.2(N2) R28.1 Y2.3(IN/OUT2)
UNNAMED_6_ICSI5356X_I34_CLK0: R34.1 U3.22
UNNAMED_6_ICSI5356X_I34_CLK1: R40.1 U3.21
UNNAMED_6_ICSI5356X_I34_CLK2: R35.1 U3.18
UNNAMED_6_ICSI5356X_I34_CLK4: R36.1 U3.14
UNNAMED_6_ICSI5356X_I34_CLK6: R37.1 U3.10
UNNAMED_6_ICSI5356X_I34_SSCDIS: R30.2(N2) R31.1 U3.5
UNNAMED_6_ICSI5356X_I34_XA: U3.1 Y3.3(IN/OUT2)
UNNAMED_6_ICSI5356X_I34_XB: U3.2(XB) Y3.1
UNNAMED_6_RES_I4_N2: R18.2(N2) R20.1 R22.1
UNNAMED_6_RES_I38_N1: R19.2(N2) R21.1 R23.1
UNNAMED_6_RES_I72_N1: R141.1 Y4.3
UNNAMED_6_RES_I73_N1: R142.1 Y5.3
UNNAMED_6_RES_I74_N1: R144.1 Y6.3
UNNAMED_6_RES_I75_N2: R143.2(N2) Y6.1
UNNAMED_6_RES_I76_N2: R140.2(N2) Y5.1
UNNAMED_6_RES_I77_N2: R139.2(N2) Y4.1
UNNAMED_7_CN100PV2_I6_N44: J3.87 R41.2(N2)
UNNAMED_7_CN100PV2_I6_N45: J3.89 R42.2(N2)
UNNAMED_7_CN100PV2_I6_N46: J3.91 R43.2(N2)
UNNAMED_7_CN100PV2_I6_N47: J3.93 R44.2(N2)
UNNAMED_7_CN100PV2_I6_N48: J3.95 R45.2(N2)
UNNAMED_8_ICIS25LP512_I14_SCK: R49.2(N2) R50.1 U4.16
UNNAMED_8_ICIS25LP512_I14_SO: R51.2(N2) R52.1 U4.8
UNNAMED_9_ADSPSC59X_I10_HADC0VREFN: R58.1 U1.N20
UNNAMED_9_ADSPSC59X_I10_HADC0VREFP: C177.1 C178.1 FL2.3(OUT) U1.R19
UNNAMED_9_DIOLED_I5_N: DS6.C R59.1
UNNAMED_10_7408V3_I4_Y: U11.4(Y) U13.1
UNNAMED_10_7408V3_I7_B: R70.2(N2) S2.2A S2.2B(N4) U13.2
UNNAMED_10_7408V3_I7_Y: R71.2(N2) U13.4(Y) U14.3
UNNAMED_10_DIOLED_I24_N: DS5.C R73.1
UNNAMED_10_DIOLED_I40_N: DS4.C R77.1
UNNAMED_10_DIOLED_I62_N: DS1.C R76.1
UNNAMED_10_DIOLED_I63_N: DS2.C R74.1
UNNAMED_10_DIOLED_I64_N: DS3.C R72.1
UNNAMED_10_ICMC23018_I57_ADDR: R64.2(N2) R65.1 U24.11
UNNAMED_10_ICMC23018_I57_GPA0: R76.2(N2) U24.15
UNNAMED_10_ICMC23018_I57_GPA1: R74.2(N2) U24.16
UNNAMED_10_ICMC23018_I57_GPA2: R72.2(N2) U24.17
UNNAMED_12_CAP_I12_N1: C185.1 C186.1 E1.2(N2) U15.19
UNNAMED_12_CAP_I23_N1: C187.1 C188.1 R88.1 U15.1(VCCIO) U15.16
UNNAMED_12_CMOSPI3C3125_I39_B0: R86.2(N2) U7.3 U15.8
UNNAMED_12_CMOSPI3C3125_I39_B1: R87.2(N2) U7.6 U15.32
UNNAMED_12_CMOSPI3C3125_I39_B2: U7.8 U15.2
UNNAMED_12_CMOSPI3C3125_I39_B3: U7.11 U15.30
UNNAMED_12_CN10PODDEVEN_I8_N5: P6.10(N5) R85.1
UNNAMED_12_DIOLED_I30_N: DS7.C R89.1
UNNAMED_12_DIOLED_I31_N: DS8.C R90.1
UNNAMED_12_ICFT232RQ_I37_CBUS0: R89.2(N2) U15.22
UNNAMED_12_ICFT232RQ_I37_CBUS1: R90.2(N2) U15.21
UNNAMED_12_ICFT232RQ_I37_RESET: R88.2(N2) U15.18
UNNAMED_13_ADLT8636_I1_BST: C207.1 VR1.7
UNNAMED_13_ADLT8636_I1_EN: R95.2(N2) R96.2(N2) VR1.14
UNNAMED_13_ADLT8636_I1_FB1: C210.2(N2) R105.2(N2) R106.1 VR1.19 VR1.20
UNNAMED_13_ADLT8636_I1_RT: R98.1 VR1.17
UNNAMED_13_ADLT8636_I1_SW1: C207.2(N2) L3.1 VR1.8 VR1.9 VR1.10
UNNAMED_13_ADLT8636_I1_SYNC: R93.1 R94.1 VR1.15
UNNAMED_13_ADLT8636_I1_TR: C204.1 VR1.18
UNNAMED_13_ADLTC3307_I3_FB: C220.2(N2) R108.2(N2) R109.1 U17.12
UNNAMED_13_ADLTC3307_I3_MODE: R5.2(N2) U17.9
UNNAMED_13_ADLTC3307_I3_SW1: L4.1 U17.5 U17.6
UNNAMED_13_ADLTC3310_I4_FB: C208.2(N2) C209.1 R97.2(N2) R101.2(N2) R102.1 R107.1 U16.18
UNNAMED_13_ADLTC3310_I4_ITH: C193.1 C195.1 R97.1 U16.17
UNNAMED_13_ADLTC3310_I4_PGOOD: R99.1 U16.14
UNNAMED_13_ADLTC3310_I4_SSTT: C202.1 U16.16
UNNAMED_13_ADLTC3310_I4_SW1: L2.1 U16.6 U16.7 U16.8 U16.9
UNNAMED_13_CAP_I72_N2: C195.2(N2) R91.1
UNNAMED_13_RES_I58_N2: R102.2(N2) R103.1
UNNAMED_14_CAP_I4_N1: C232.1 U19.C2
UNNAMED_14_CMOSSN74CB3T3125_I44_2B: R68.1 R119.2(N2) U12.6
UNNAMED_14_ICIS2XES04G_I1_CLK: R110.2(N2) U19.M6
UNNAMED_16_CAP_I2_N1: C158.1 D15.C D16.A(P) P1.A4 P1.A9 P1.B4 P1.B9(N9) Q4.5 Q4.6 Q4.7 Q4.8 R67.1 R123.1
UNNAMED_16_CAP_I15_N1: C159.1 D16.C R123.2(N2) R124.1
UNNAMED_16_CAP_I20_N1: C199.1 U6.21
UNNAMED_16_CAP_I21_N1: C200.1 U6.23
UNNAMED_16_CAP_I27_N2: C160.2(N2) R130.2(N2)
UNNAMED_16_CAP_I38_N1: C184.1 P1.SH1 P1.SH2 P1.SH3 P1.SH4 P1.SH5 P1.SH6 R80.1
UNNAMED_16_CN24PAB2GND6SHLD_I6_N5: D17.3 P1.A5 R6.1 U6.1 U6.2
UNNAMED_16_CN24PAB2GND6SHLD_I7_N5: D17.1 P1.B5 R66.1 U6.4 U6.5
UNNAMED_16_ICSTUSB4500_I31_ADDR0: R125.1 U6.12
UNNAMED_16_ICSTUSB4500_I31_ADDR1: R126.1 U6.13
UNNAMED_16_ICSTUSB4500_I31_DISCH: R146.2(N2) U6.9
UNNAMED_16_ICSTUSB4500_I31_VBUSENSNK: R129.2(N2) U6.16
UNNAMED_16_ICSTUSB4500_I31_VBUSVSDISCH: R124.2(N2) U6.18
UNNAMED_16_RES_I22_N2: Q4.4 Q5.4 R128.2(N2) R129.1 R130.1
USB_DM: D2.1 P1.A7 P1.B7 U15.15
USB_DP: D2.2 P1.A6 P1.B6 U15.14
USB_TYPEC: C160.1 C183.1 C201.1 D1.1 D18.C E1.1 JP1.1 Q4.1 Q4.2 Q4.3(S3) Q5.1 Q5.2 Q5.3(S3) Q5.5 Q5.6 Q5.7 Q5.8 R67.2(N2) R128.1 R146.1 U6.24
VTT: C9.1 C10.1 C12.1 C14.1 C15.1 C16.1 C17.1 C18.1 C19.1 C20.1 C21.1 C22.1 C23.1 C24.1 C25.1 C26.1 C29.1 C31.1 C33.1 C35.1 C37.1 C41.1 C42.1 C43.1 C245.1 C246.1 RN1.5 RN1.6 RN1.7 RN1.8(N8) RN2.5 RN2.6 RN2.7 RN2.8(N8) RN3.5 RN3.6 RN3.7 RN3.8(N8) RN4.5 RN4.6 RN4.7 RN4.8(N8) RN5.5 RN5.6 RN5.7 RN5.8(N8) RN6.5 RN6.6 RN6.7 RN6.8(N8) RN7.7 RN7.8(N8) U2.6 U2.9(VTT)

Pads without a net: D1 3 4 6; D2 4 5 6 7 9 10; D17 4 5; J1 57 59 61 63 65 67 69 71 73 75 84; J2 29 53 73 74 75 77; P1 A2 A3 A8 A10 A11 B2 B3 B8 B10 B11; P6 7; RN7 3 4 5 6; S1 8; U2 5; U3 8 9 13 17; U4 4 5 6 11 12 13 14; U6 11 14 15 17 20; U8 J1 J9 L1 L9; U15 3 5 6 7 9 10 11 12 13 23 25 27 28 29 31; U18 4; U19 A1 A2 A7 A8 A9 A10 A11 A12 A13 A14 B1 B7 B8 B9 B10 B11 B12 B13 B14 C1 C3 C5 C7 C8 C9 C10 C11 C12 C13 C14 D1 D2 D3 D4 D12 D13 D14 E1 E2 E3 E5 E8 E9 E10 E12 E13 E14 F1 F2 F3 F10 F12 F13 F14 G1 G2 G3 G10 G12 G13 G14 H1 H2 H3 H5 H12 H13 H14 J1 J2 J3 J12 J13 J14 K1 K2 K3 K6 K7 K10 K12 K13 K14 L1 L2 L3 L12 L13 L14 M1 M2 M3 M7 M8 M9 M10 M11 M12 M13 M14 N1 N3 N6 N7 N8 N9 N10 N11 N12 N13 N14 P1 P2 P7 P8 P9 P10 P11 P12 P13 P14; U23 11 12; U24 2 3 4 5 6 7 13 14 22; U25 11 12; VR1 5 12 16

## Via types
v1: diameter 0.432, hole 0.203, TOP to BOTTOM, 1206 vias
v2: diameter 0.635, hole 0.305, TOP to BOTTOM, 539 vias
v3: diameter 0.203, hole 0.102, TOP to L2_PWR, 8 vias

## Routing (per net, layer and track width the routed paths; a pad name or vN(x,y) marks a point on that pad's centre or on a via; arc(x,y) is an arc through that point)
DGND: length 448.4
  TOP w0.14: v1(49.15,23.05) 48.93,22.83 48.18,22.83 U3.6 ; U19.H10 v1(47.71,37.83) ; v1(51.12,34.38) U19.P4 U19.N5 U19.P6 v1(51.12,35.38) ; U19.J5 v1(48.21,34.43) ; v1(46.67,36.13) 46.42,35.88 U19.E7 ; U19.G5 v1(47.21,34.43) ; U19.K8 v1(49.16,36.38) ; U19.A6 v1(43.31,35.38)
  TOP w0.203: U1.C3 v1(27.42,59.74) ; U8.T9 38.99,79.57 v1(38.62,79.94) ; U1.G1 v1(25.02,55.74) U1.H1 ; U1.W2 v1(25.82,46.14) ; U1.G8 v1(31.42,55.74) U1.G9 ; U1.N12 v1(34.62,50.94) ; U1.M20 v1(40.22,52.54) ; U1.P8 v1(30.62,50.94) U1.N8 ; U1.E16 v1(37.02,57.34) U1.F15 ; U1.P9 v1(31.42,50.94) ; v1(41.02,45.34) U1.Y20 ; v1(31.42,79.94) 31.42,79.94 U8.G9 ; U1.T1 v1(25.02,48.54) ; U1.T8 v1(30.62,48.54) ; U1.L14 v1(35.42,53.34) U1.L13 ; U1.T5 v1(28.22,48.54) ; U1.R6 v1(29.02,49.34) ; U1.J7 v1(30.62,54.14) U1.J8 ; U8.T1 v1(38.62,72.74) ; U8.J2 v1(33.02,73.54) ; U1.F6 v1(29.82,57.34) ; U1.E5 v1(28.22,58.14) U1.D4 ; U8.E2 v1(29.82,74.34) ; U1.L8 v1(30.62,52.54) ; v1(35.42,79.94) 35.42,79.94 U8.M9 ; U1.P1 v1(25.02,50.14) ; U1.W19 v1(40.22,46.14) ; U1.U4 v1(27.42,47.74) ; U1.N11 v1(33.82,50.94) ; U1.J14 v1(36.22,54.94) ; U1.J9 v1(32.22,54.14) U1.J10 ; U1.K1 v1(25.02,54.14) ; v1(25.82,60.54) U1.B2 ; U1.G7 v1(29.82,56.54) ; U1.N10 v1(33.02,50.94) ; v1(30.62,79.94) 30.62,79.94 U8.F9 ; U1.L7 v1(29.82,52.54) U1.L6 ; U1.C18 v1(38.62,58.94) U1.D17 ; U1.N13 v1(35.42,50.94) U1.P13 ; U1.L15 v1(36.22,52.54) ; U8.G1 v1(31.42,72.74) ; U8.M1 v1(35.42,72.74) ; U8.B3 v1(28.22,74.34) ; U1.J13 v1(34.62,54.14) U1.J12 ; U8.D1 v1(29.02,72.74) ; U1.R15 v1(37.02,49.34) ; v1(33.02,52.54) U1.L11 ; U1.V18 v1(39.42,46.94) ; U1.E13 v1(35.42,58.14) ; U8.P9 37.39,79.57 v1(37.02,79.94) ; v1(33.02,79.14) 33.39,78.77 U8.J8 ; U1.G10 v1(33.02,55.74) U1.G11 ; U1.L10 v1(32.22,52.54) U1.L9 ; U1.A1 v1(25.02,61.34) ; U1.P14 v1(36.22,50.94) ; U1.T16 v1(37.82,48.54) ; U1.V3 v1(26.62,46.94) ; U1.J11 v1(33.02,54.14) ; U1.G15 v1(37.02,56.54) ; U1.M1 v1(25.02,51.74) ; v1(26.62,79.94) 26.62,79.94 U8.A9 ; U8.B9 v1(27.42,79.94) ; U8.B1 v1(27.42,72.74) ; v1(29.02,54.94) U1.J6 ; U1.A20 v1(41.02,61.34) ; U8.P1 v1(37.02,72.74) ; U1.Y1 v1(25.02,45.34) ; U8.E8 v1(30.62,79.14) ; U1.L12 v1(33.82,52.54) ; U1.U17 v1(38.62,47.74) ; U1.B19 v1(40.22,60.54) ; U1.E9 v1(31.42,58.14) ; U8.D8 v1(29.82,79.14) ; U1.P7 v1(29.82,50.94) ; U8.E1 v1(29.82,73.54) ; U8.G8 v1(31.42,79.14)
  TOP w0.254: 49.92,24.32 v1(50.16,24.07) 49.92,23.82 U3.4 ; 49.92,24.32 49.41,24.82 U3.23 ; 49.92,24.32 U3.3 ; v1(38.62,72.74) 38.61,72.73 38.61,72.14 ; U2.8 v2(55.37,71.69) U2.PAD v2(55.37,70.68) U2.3 ; v1(35.42,72.74) 35.42,72.15 ; v1(24,29.1) 24.27,29.36 U21.7 ; v2(30.54,18.16) 30.54,17.82 U16.10 ; 46.11,94.49 v2(46.36,94.49) ; 35.12,15.62 34.68,15.62 34.16,16.14 U16.2 32.76,16.14 v2(32.64,16.26) ; U15.20 13.43,86.61 14.36,86.61 v2(14.61,86.36) ; v2(12.45,88.25) 12.45,88.25 12.45,88.27 12.83,88.27 12.98,88.11 U15.17 ; 37.02,72.07 v1(37.02,72.74) ; P1.B1 27.73,92.22 P1.A12 ; v2(15.88,86.36) 14.63,85.11 U15.26 ; U16.5 33.72,17.82 v2(33.72,18.16) ; U1.J15 v1(36.22,54.94) ; U15.24 v2(12.16,84.61)
  TOP w0.305: R65.2 v2(13.59,67.75) ; v1(29.22,65.54) C68.2 ; C81.2 v1(20.62,59.74) ; U6.22 46.11,94.49 ; C79.2 v1(37.02,65.54) ; U22.PAD v1(30.29,30.93) 30.17,30.82 U22.7 ; v1(21.22,40.94) 21.53,41.25 C80.2 ; v1(36.2,30.93) 36.08,30.82 U25.7 ; C83.2 v1(30.62,65.54) ; v2(29.53,88.27) 29.84,88.58 D17.2 ; v1(32.02,65.54) C88.2 ; C77.2 v1(48.62,51.74) ; v1(27.92,65.54) C73.2 ; C87.2 v1(48.62,45.34) ; v1(20.62,61.34) C120.2 ; C45.2 48.64,55.02 v2(48.62,55.04) 46.99,55.04 C44.2 ; 48.62,58.72 C178.2 v2(48.62,59.54) 47.22,59.54 C177.2 ; v1(20.62,50.54) 20.87,50.29 C164.2 ; v1(18.99,44.01) C157.2 ; v1(36.2,36.19) 36.08,36.08 U23.7 ; v1(27.42,40.94) C143.2 ; v2(56.52,9.52) C247.2 55.92,8.57 55.28,9.2 U26.5 ; v2(52.07,93.22) D18.A ; D2.3 D2.8 v2(13.97,92.07) ; U7.7 11.43,75.14 v2(11.05,74.93) ; C158.2 v2(26.08,89.09) ; C159.2 v2(36.83,90.41) ; C74.2 v1(45.42,58.14) ; v2(46.36,94.49) U6.PAD ; U6.PAD 46.6,93.22 U6.10 ; U6.PAD 46.11,93.72 U6.3 ; v1(24.22,40.94) C127.2 ; v1(22.62,40.94) C163.2 ; C180.2 58.04,41.2 v1(58.04,41.78) ; v1(58.29,28.83) 58.23,28.83 ; 58.23,28.83 58.29,28.77 58.29,28.19 58.04,27.94 58.04,27.42 C182.2 57.92,27.28 57.42,26.78 U14.1 ; 58.23,28.83 57.34,28.83 U13.3 ; C181.2 58.04,32.5 v1(58.04,34.29) 56.54,34.29 S2.1A ; v1(25.82,40.94) C64.2 ; S2.1B 61.82,34.13 v1(61.85,34.16) ; D15.A v2(26.47,87.38) ; U1.N9 v1(31.42,50.94) ; Y3.2 46.56,24.89 v1(47.05,24.89) ; v1(45.42,48.54) C82.2 ; v1(48.63,61.37) 48.62,61.37 48.62,61.34 C146.2 ; v2(34.92,19.49) C191.2 ; C86.2 v1(20.62,46.34) ; v2(41.02,89.16) R127.2 ; C149.2 v1(33.82,40.94) ; C96.2 v1(20.62,54.14) ; v2(29.49,19.49) C192.2 ; v1(35.42,65.54) C69.2 ; C135.2 v1(29.02,40.94) ; P1.A1 33.23,92.22 P1.B12 ; U20.7 30.17,36.08 v1(30.29,36.19) ; C171.2 v1(53.59,25.97) ; C179.2 v2(17.14,66.81) ; v1(45.42,50.14) C133.2 ; C139.2 v1(32.22,40.94) ; U4.10 8.89,36.96 v1(8.26,37.59) ; C169.2 v1(18.02,48.74) ; v2(51.31,8.26) U26.2 ; v1(55.25,37.34) 55.75,37.78 57.27,37.78 U11.3 ; R31.2 v1(44.13,22.79) ; C229.2 31.62,28.45 v1(31.31,28.13) ; v2(41.73,93.73) R6.2 ; C109.2 34.99,40.63 v1(35.42,40.2) ; C100.2 21.15,52.94 v1(20.62,52.94) ; v2(41.73,92.2) R66.2 ; C172.2 v1(51.5,19.04) ; v1(38.62,65.54) C84.2 ; C116.2 v1(20.62,56.54) ; v1(45.42,61.34) C134.2 ; v1(25.22,65.54) C78.2 ; C62.2 v1(45.42,45.34) ; v2(14.29,12.17) R93.2 ; 24.38,36.19 24.27,36.08 U12.7 ; v2(17.21,9.6) C204.2 ; C153.2 v1(45.42,62.94) ; C104.2 v1(20.62,49.14) ; v1(48.62,50.14) C67.2 47.87,50.14 ; C70.2 v1(30.62,40.94) ; C130.2 v1(48.62,62.94) ; C72.2 v1(48.62,46.94) ; Y3.4 v1(43.86,27.3) ; C58.2 v1(26.62,65.54) ; v1(45.42,46.94) R113.2 ; C138.2 v1(45.42,59.74) ; R58.2 v1(45.42,51.74) ; v2(7.37,64.81) R77.2 ; C91.2 v1(20.62,55.34) ; v1(20.62,58.14) C60.2 ; C129.2 v1(48.62,48.54) ; R57.2 v1(20.62,63.14) ; v2(16.13,9.63) R98.2 ; v1(40.22,65.54) C150.2
  TOP w0.356: C40.2 42.02,77.97 v1(42.02,78.54) 42.02,79.11 R10.2 ; C28.2 42.02,74.77 v1(42.02,75.34) 42.02,75.91 C32.2 ; C30.2 42.02,71.57 v1(42.02,72.14) 42.02,72.71 C34.2
  TOP w0.406: v1(30.62,69.41) C7.2 ; v1(28.22,83.34) C1.2 ; v1(29.82,83.34) C5.2 ; v1(28.22,69.41) C6.2 ; 37.82,69.53 C8.2 ; v2(61.59,68.07) 60.54,68.07 C11.2 60.54,67.31 v2(61.59,67.31) ; v1(34.62,83.34) R4.2 ; C3.2 v1(37.82,83.34) ; v1(32.22,83.34) C2.2
  TOP w0.508: Y1.2 v2(14.39,50.05) ; D1.5 v2(17.78,92.71) D1.2 ; R126.2 v2(49.33,89.16) ; R50.2 v2(10.92,26.54) ; R79.2 v2(10.79,46.36) ; U10.3 v2(8.88,39.5) ; Y2.2 v2(14.39,44.92) ; C254.2 v2(53.87,67.87) ; C167.2 v2(13.96,44.39) ; C168.2 v2(16.64,53.89) ; C36.2 v2(52.22,68.9) ; P6.5 2.79,52.45 ; R125.2 v2(46.86,89.16) ; v2(51.69,57.79) C228.2 53.59,57.79 54.74,58.93 U18.2 ; C206.2 23.23,10.29 v2(21.39,10.29) R106.2 ; C166.2 v2(13.96,49.53) ; v2(17.53,39.5) 17.52,39.5 U9.3 ; 3.81,53.72 2.79,53.72 ; Y1.4 v2(12.19,53.83) ; Y2.4 v2(12.19,48.7) ; C27.2 v2(52.9,67.9) ; U5.3 v2(13.2,39.5)
  L2_PWR w0.14: v3(50.21,33.38) v1(50.21,32.3)
  L3_GND w0.508: 28.48,91.58 P1.GND2 ; 2.88,52.45 P6.5 ; 33.97,92.27 P1.B12 33.28,91.58 ; 27.68,91.58 P1.B1 26.99,92.27 ; 2.88,53.72 3.81,53.72 ; 32.48,91.58 P1.GND1
  L7_SIG w0.508: 27.68,91.58 P1.B1 26.99,92.27 ; 28.48,91.58 P1.GND2 ; 33.28,91.58 P1.B12 33.97,92.27 ; 32.48,91.58 P1.GND1
  L9_GND w0.406: 25.66,95.47 25.76,95.36 ; 34.3,95.47 34.4,95.36 ; 26.66,95.47 26.56,95.36 ; 35.3,95.47 35.2,95.36
  L9_GND w0.508: 2.88,52.45 P6.5 ; 32.48,91.58 P1.GND1 ; 27.68,91.58 P1.B1 26.99,92.27 ; 2.88,53.72 3.81,53.72 ; 33.28,91.58 P1.B12 33.97,92.27 ; 28.48,91.58 P1.GND2
  BOTTOM w0.14: C234.2 46.68,36.14 v1(46.67,36.13) ; C232.2 v1(46.99,32) ; C235.2 v1(45.66,37.66) ; 27.11,26.1 27.11,26.35 27.75,26.99 27.75,27.3 28.51,28.07 29.84,28.07 30.48,28.7 30.48,29.97 30.99,30.48 31.88,30.48 32.8,31.4 32.8,32.54 33.27,33.02 33.27,35.5 32.83,35.94 32.83,37.78 33.21,38.16 33.21,38.5 32.87,38.84 32.87,43.87 33.02,44.03 v1(33.02,50.94)
  BOTTOM w0.254: 27.68,91.58 P1.B1 ; v1(35.42,58.14) 34.72,57.44 C118.2 ; 28.48,91.58 P1.GND2 ; P1.GND1 P1.B12
  BOTTOM w0.305: v1(1.52,36.45) 1.65,36.32 J3.25 ; J3.2 5.71,43.94 v1(5.33,44.2) ; v1(31.42,58.14) C122.2 31.42,57.42 ; v1(58.24,29.84) 58.08,29.84 57.78,29.97 J1.56 ; v2(19.81,81.66) C187.2 19.81,82.48 ; C50.2 16.42,50.64 v1(16.42,49.54) ; C132.2 31.42,50.7 v1(31.42,50.94) ; J2.24 22.91,5.71 v1(23.11,5.33) ; J1.2 57.66,12.83 v1(58.04,12.83) ; C125.2 v1(48.62,45.34) ; v1(33.82,40.94) C149.2 ; C176.2 v2(20.51,30.61) ; C164.2 20.87,50.29 v1(20.62,50.54) ; v2(35.18,89.6) C43.2 ; v1(20.62,46.34) C71.2 ; J2.1 15.92,2.16 v1(15.88,1.65) ; J2.51 31.8,2.03 v1(31.88,1.65) ; v1(20.62,52.94) 21.15,52.94 C100.2 ; C152.2 29.82,50.7 v1(29.82,50.94) ; C65.2 29.12,57.34 v1(29.82,57.34) ; v1(50.21,32.3) 50.18,32.33 C236.2 ; v1(37.08,5.33) 36.88,5.71 J2.68 ; C69.2 v1(35.42,65.54) ; v1(40.77,4.44) 40.69,4.06 J2.79 ; v1(30.62,50.94) C108.2 ; v1(35.18,84.96) C10.2 ; v1(26.62,65.54) C58.2 26.62,64.79 ; J3.60 7.87,25.53 v1(8.26,25.4) ; v1(33.02,54.14) 33.72,54.14 C112.2 ; v1(45.42,54.94) R1.2 ; J1.45 58.8,26.8 v1(58.42,26.54) ; J3.36 5.84,33.15 v1(5.46,33.15) ; v1(51.62,46.14) 50.72,46.14 C57.2 50.12,46.14 v1(49.32,46.14) ; v2(23.3,94.74) R80.2 ; R56.2 18.29,40.26 v2(17.53,39.5) ; J2.2 15.92,7.62 v1(15.88,8.13) ; v1(47.05,24.89) 47.05,24.26 C170.2 ; v1(24.38,37.46) 24.9,37.98 C238.2 ; v1(45.42,50.14) C113.2 ; C137.2 v1(45.42,51.74) ; v2(1.27,69.85) R25.2 ; v2(14.73,80.52) R84.2 ; v1(24.38,32.2) 24.84,32.66 C240.2 ; v2(40.26,82.55) 40.26,83.39 40.56,83.69 C17.2 41.28,83.69 v2(41.28,82.55) ; 36.22,54.24 36.3,54.17 ; 36.22,54.24 36.3,54.17 ; 36.22,54.24 v1(36.22,54.94) ; 36.3,54.17 C90.2 ; C237.2 v2(52.38,32.33) ; v1(23.75,1.65) 23.54,2.16 J2.25 ; C85.2 v1(46.23,40.5) ; C162.2 v1(38.62,65.54) ; v1(30.48,5.33) 30.53,5.71 J2.48 ; J3.1 2.03,43.94 v1(1.52,44.2) ; v1(61.72,30.1) 61.22,29.97 J1.55 ; v1(31.42,55.74) 31.52,55.64 C59.2 ; v1(20.62,51.74) 20.8,51.56 C61.2 ; C23.2 41.52,65.27 v1(41.52,64.74) ; v1(30.62,52.54) 30.31,52.54 C242.2 30.15,52.54 v1(29.82,52.54) ; v1(9.4,15.75) 9.02,16 J3.90 ; v1(45.42,59.74) 44.73,59.74 C48.2 ; 43.69,81.92 C9.2 ; 43.69,81.91 v1(43.69,82.3) ; 43.69,81.91 42.93,81.91 v2(42.29,82.55) ; C130.2 v1(48.62,62.94) ; 35.31,8.57 34.97,8.24 J2.62 ; C105.2 v1(48.62,50.14) ; v1(43.69,72.01) 43.69,72.01 C14.2 ; R17.2 19.52,56.54 v1(18.82,56.54) ; v1(9.14,21.84) 9.14,21.21 8.38,20.45 J3.76 ; J1.94 57.66,42.04 v1(58.04,41.78) ; v1(58.8,12.83) 59.18,12.83 J1.1 ; v1(42.52,64.74) 42.52,65.24 C12.2 ; v2(14.61,87.63) 14.1,87.12 C186.2 ; v1(51.12,35.38) 51.62,35.88 C233.2 ; J2.71 38.15,2.03 v1(38.1,1.65) ; v1(20.62,49.14) C104.2 21.37,49.14 ; C101.2 v1(48.62,46.94) ; v1(20.62,56.54) C116.2 ; C97.2 v1(45.42,45.34) ; v1(1.4,17.27) 1.91,17.27 J3.85 ; C143.2 v1(27.42,40.94) ; v1(8.51,12.7) 8,12.83 J3.100 ; v1(20.62,55.34) C91.2 ; J3.22 7.87,37.59 v1(8.25,37.59) ; C76.2 36.12,55.74 v1(35.42,55.74) ; v1(45.59,63.88) 45.59,64.29 45.34,64.54 C98.2 ; v1(36.2,37.46) 36.2,37.59 36.58,37.98 C249.2 ; C120.2 v1(20.62,61.34) ; C103.2 v1(21.22,40.94) ; J3.39 2.03,31.88 v1(1.52,32) ; v2(51.44,43.94) 51.24,43.75 C49.2 ; C111.2 v1(45.15,40.31) ; J1.87 61.21,40.13 v1(61.72,40.51) ; C115.2 v1(47.31,40.31) ; C239.2 30.61,38.67 v1(30.61,39.43) ; C141.2 v1(48.62,48.54) ; v2(23.3,100.58) C184.2 ; C128.2 35.29,50.81 v1(35.42,50.94) ; R95.1 14.45,14.54 v2(12.38,14.54) ; C95.2 v1(30.62,40.94) ; v2(16,80.52) C189.2 ; v1(45.42,48.54) C145.2 ; C221.2 C212.2 27.11,25.59 27.11,26.1 ; v1(29.02,40.94) C135.2 ; C54.2 17.9,44.07 v1(17.08,44.07) ; v1(48.63,61.37) 48.62,61.37 48.62,61.34 C146.2 ; v2(16,73.91) R82.2 ; C99.2 v1(25.82,40.94) ; v1(8.26,29.84) 7.87,29.97 J3.46 ; v1(36.22,50.94) 36.35,50.81 C136.2 ; J1.44 55.81,26.16 55.5,26.47 v1(55.5,26.8) 55.5,26.8 J1.46 ; v1(61.72,26.29) 61.22,26.16 J1.43 ; v2(14.22,57.54) 14.48,57.28 C55.2 ; 32.37,53.34 C244.2 32.32,52.64 v1(32.22,52.54) 32.32,52.44 C46.2 ; R115.2 20.07,34.81 v1(20.32,35.05) ; C60.2 v1(20.62,58.14) ; C92.2 v1(48.62,51.74) ; v1(21.82,65.54) C53.2 ; v2(18.54,81.66) C188.2 ; C18.2 v1(43.69,75.31) ; v1(45.42,62.94) 44.23,62.94 C94.2 ; C131.2 v1(24.22,40.94) ; C147.2 v1(41.91,40.46) ; C250.2 36.52,32.53 v1(36.2,32.2) ; C119.2 v1(42.99,40.31) ; C243.2 24.56,54.14 v1(25.02,54.14) ; C150.2 v1(40.22,65.54) ; C16.2 v1(43.69,78.49) ; C148.2 v1(20.62,47.74) ; v2(36.45,89.6) C246.2 ; v1(32.22,40.94) C139.2 ; v2(37.72,89.6) C42.2 ; J3.41 2.03,31.24 v1(1.52,31.11) ; C107.2 v1(44.07,40.46) ; v1(40.77,5.33) 40.69,5.71 J2.80 ; J3.98 v1(8.51,13.46) ; C163.2 v1(22.62,40.94) ; C81.2 v1(20.62,59.74) ; C74.2 v1(45.42,58.14) ; v1(20.62,54.14) C96.2 ; v1(30.29,32.2) 30.29,32.94 C241.2 ; v1(33.02,55.74) C156.2 ; R117.2 v2(36.76,28.2) ; v1(45.42,46.94) C121.2
  BOTTOM w0.381: v2(13.49,31.62) C252.2 ; v2(13.48,23.62) 13.46,23.64 Y6.2 ; R54.2 v2(13.2,39.5) ; Y4.2 13.35,33.16 v2(12.19,33.16) ; C253.2 14.28,27.37 v2(13.47,27.37) 13.46,27.38 Y5.2 ; C175.2 v2(20.64,41.09) ; C174.2 v2(10.99,39.46) ; v1(36.25,40.01) 36.25,40.81 C52.2 35.42,40.84 v1(35.42,40.2) ; v2(14.17,36.82) C251.2
  BOTTOM w0.406: C4.2 v1(48.62,56.54)
  BOTTOM w0.508: C200.2 44.74,94.49 v2(45.34,94.49) ; C185.2 v2(8.64,87.12) ; C183.2 v2(20.83,93.24) ; 3.81,53.72 2.86,53.72 ; v2(47.37,94.49) 48.35,94.49 C199.2 ; P6.5 2.79,52.45 ; v2(9.65,80.9) 9.39,80.64 R24.2 ; R26.2 v2(1.71,79.69)
  vias: v1(14.1,63.37) v1(14.1,62.61) v1(14.1,61.85) v1(14.86,63.37) v1(14.86,62.61) v1(14.86,61.85) v1(15.62,63.37) v1(15.62,62.61) v1(15.62,61.85) v1(16,5.33) v1(19.81,66.29) v1(19.81,65.15) v1(19.81,63.37) v1(21.72,1.65) v1(24.38,30.93) v1(24.51,1.65) v1(24.7,36.2) v1(25.65,37.46) v1(25.65,36.19) v1(25.65,32.2) v1(25.65,30.93) v1(27.05,1.65) v1(28.57,4.44) v1(30.29,37.46) v1(31.56,37.46) v1(31.56,36.19) v1(31.56,32.2) v1(31.56,30.93) v1(35.94,4.44) v1(36.83,36.83) v1(36.83,31.57) v1(37.47,37.46) v1(37.47,36.19) v1(37.47,32.2) v1(37.47,30.93) v1(38.8,85.03) v1(40.26,1.65) v1(42.8,1.65) v1(45.09,14.92) v1(46.36,34.38) v1(49.15,25.08) v1(49.15,24.07) v1(50.16,25.08) v1(50.16,23.05) v1(51.18,25.08) v1(51.18,24.07) v1(51.18,23.05) v1(54.86,45.72) v1(58.04,20.19) v1(58.04,16.76) v1(58.8,18.8) v1(61.72,42.29) v1(61.72,38.99) v2(1.4,92.96) v2(1.4,62.23) v2(1.4,58.42) v2(1.4,29.34) v2(1.4,27.3) v2(1.52,78.49) v2(1.52,74.8) v2(1.52,71.5) v2(1.52,67.94) v2(2.67,76.83) v2(4.57,73.79) v2(6.73,76.83) v2(6.73,74.55) v2(6.73,71.25) v2(8.26,1.9) v2(9.91,77.6) v2(10.16,67.82) v2(10.35,89.92) v2(10.54,14.54) v2(10.54,13.78) v2(10.79,25.27) v2(11.18,89.92) v2(11.3,14.54) v2(11.3,13.78) v2(11.43,5.84) v2(11.68,25.27) v2(12.19,82.68) v2(12.45,25.27) v2(12.7,91.44) v2(12.7,1.9) v2(13.97,8.13) v2(14.48,4.44) v2(14.61,85.09) v2(14.86,82.68) v2(15.37,59.56) v2(15.88,87.63) v2(15.88,85.09) v2(17.14,87.63) v2(17.14,86.36) v2(17.14,85.09) v2(17.53,16.26) v2(17.53,15.24) v2(17.53,14.22) v2(18.54,16.26) v2(18.54,15.24) v2(18.54,14.22) v2(19.05,89.53) v2(19.81,86.74) v2(22.99,73.66) v2(24.76,25.84) v2(24.76,24.96) v2(24.76,24) v2(24.76,22.42) v2(24.76,21.46) v2(24.76,20.83) v2(24.76,14.61) v2(24.76,13.92) v2(25.4,22.1) v2(25.4,21.46) v2(25.4,20.83) v2(25.59,14.67) v2(25.59,13.92) v2(31.11,83.82) v2(31.62,17.02) v2(31.62,16.26) v2(32.64,17.02) v2(36.58,15.3) v2(38.29,20.13) v2(39.31,27.3) v2(39.31,26.35) v2(39.31,24.7) v2(39.31,23.81) v2(39.31,22.86) v2(39.5,19.68) v2(39.5,18.92) v2(39.5,18.16) v2(40.51,19.68) v2(40.51,18.92) v2(40.51,18.16) v2(41.4,19.68) v2(41.4,18.92) v2(41.4,18.16) v2(43.43,30.48) v2(45.34,93.47) v2(45.34,92.46) v2(46.36,92.46) v2(47.18,11.43) v2(47.37,93.47) v2(47.37,92.46) v2(48.01,13.33) v2(48.01,11.43) v2(48.01,4.13) v2(48.13,8) v2(48.13,1.65) v2(48.58,19.75) v2(48.58,18.99) v2(48.58,18.22) v2(49.53,19.75) v2(49.53,18.99) v2(49.53,18.22) v2(50.16,63.25) v2(51.02,59.64) v2(51.18,63.25) v2(51.18,1.78) v2(51.75,77.79) v2(51.75,77.03) v2(51.75,76.26) v2(51.75,75.5) v2(51.75,74.74) v2(52.51,77.79) v2(52.51,77.03) v2(52.51,76.26) v2(52.51,75.5) v2(52.51,74.74) v2(52.71,87.5) v2(52.71,86.23) v2(52.71,84.96) v2(52.71,83.69) v2(53.09,47.37) v2(53.66,71.31) v2(53.66,70.68) v2(53.98,87.5) v2(53.98,86.23) v2(53.98,84.96) v2(53.98,83.69) v2(54.23,33.65) v2(54.61,71.69) v2(54.61,70.68) v2(55.12,12.06) v2(55.25,87.5) v2(55.25,86.23) v2(55.25,84.96) v2(55.25,83.69) v2(55.25,1.9) v2(56.13,71.69) v2(56.13,70.68) v2(56.52,81.66) v2(57.66,8.25) v2(57.79,81.28) v2(58.8,45.21) v2(59.05,9.78) v2(60.2,77.72) v2(60.2,76.96) v2(60.2,76.2) v2(60.2,75.44) v2(60.2,74.68) v2(60.2,73.91) v2(60.2,65.6) v2(60.33,80.39) v2(60.33,79.12) v2(60.58,11.3) v2(60.64,8.25) v2(60.96,77.72) v2(60.96,76.96) v2(60.96,76.2) v2(60.96,75.44) v2(60.96,74.68) v2(60.96,73.91) v2(60.96,65.6) v2(61.22,47.24) v2(61.59,80.39) v2(61.59,79.12) v2(61.59,71.12) v2(61.59,70.36) v2(61.59,69.6) v2(61.59,68.83) v2(61.72,77.72) v2(61.72,76.96) v2(61.72,76.2) v2(61.72,75.44) v2(61.72,74.68) v2(61.72,73.91) v2(61.72,73.15) v2(61.72,72.39) v2(61.72,65.6) v2(61.72,18.54) v2(61.85,35.56) v2(61.85,32.51) v2(61.98,12.45) v2(61.98,9.78) v3(45.21,34.38)
VDD_CONNECTOR: length 3.7
  BOTTOM w0.305: J3.99 4.19,12.83 v2(4.45,13.08) 4.19,13.46 4.19,13.46 J3.97
  BOTTOM w0.635: v2(4.45,13.08) v2(5.33,13.08)
VDD_DMC: length 64.8
  TOP w0.203: v1(37.82,79.94) 38.19,79.57 U8.R9 ; U8.C1 v1(28.22,72.74) ; U8.R1 v1(37.82,72.74) ; U8.B2 27.79,73.91 27.79,73.91 v1(27.42,73.54) ; U8.A8 26.99,78.77 v1(26.62,79.14) ; v1(32.22,79.94) 32.59,79.57 U8.H9 ; U8.F1 v1(30.62,72.74) ; U8.E9 29.82,79.94 v1(29.82,79.94) ; U8.N1 v1(36.22,72.74) ; v1(32.22,73.54) 32.59,73.91 32.59,73.91 U8.H2 ; v1(28.22,79.94) 28.22,79.94 U8.C9 ; U8.K8 34.19,78.77 v1(33.82,79.14) ; U1.F11 v1(33.82,57.34) ; U1.F9 v1(32.22,56.54) ; U1.F13 v1(35.42,57.34) U1.F14 ; U8.A1 v1(26.62,72.74) ; U1.F8 v1(30.62,56.54) U1.F7 ; U1.E12 v1(34.62,58.14) ; U1.E10 v1(32.22,58.14) ; U1.F12 v1(33.82,56.54) ; U1.E11 v1(33.82,58.14) ; U8.N9 36.59,79.57 v1(36.22,79.94) ; U1.F10 v1(32.22,57.34) ; U8.K2 34.19,73.91 34.19,73.91 v1(33.82,73.54) ; U8.G7 v1(31.42,77.54) ; U8.D9 v1(29.02,79.94) ; U8.D2 v1(29.02,73.54)
  TOP w0.305: C220.1 v2(45.33,10.73) ; v1(43.75,58.93) 43.75,59.71 C138.1 ; v1(37.02,63.14) C79.1 ; R108.1 v2(44.26,10.73) ; v1(46.22,62.94) C130.1 ; v1(38.62,63.14) C84.1 ; v1(43.02,62.94) C153.1 ; v1(40.22,63.14) C150.1 ; v1(46.22,61.34) C146.1 ; v1(35.42,63.14) C69.1 ; v1(43.02,58.14) C74.1 ; v1(43.02,61.34) C134.1 ; C58.1 v1(26.62,63.14)
  TOP w0.406: R9.1 v1(36.22,83.34) ; v1(37.82,79.94) C3.1 ; C8.1 v1(37.82,72.74) ; v1(30.62,72.74) C7.1 ; v1(28.22,72.74) C6.1 ; v1(39.22,69.44) R8.1 ; v1(29.82,79.94) C5.1 ; v1(32.22,79.94) C2.1 ; v1(28.22,79.94) C1.1 ; v1(32.22,69.44) C39.1
  L6_PWR w0.508: 40.21,23.48 TP3.1 ; TP3.1 42.34,21.35 ; TP3.1 40.21,21.35 ; TP3.1 42.34,23.48
  BOTTOM w0.305: v1(43.18,64.01) 43.71,64.54 C98.1 ; v1(38.62,63.14) 38.62,63.14 C63.1 ; C102.1 42.72,62.32 43.02,62.63 v1(43.02,62.94) ; J3.92 8.89,15.37 v1(9.4,14.99) ; v1(33.82,56.54) 34.52,56.54 C118.1 ; v1(23.02,63.77) 21.95,63.77 C53.1 21.69,63.77 v1(20.62,63.77) ; v1(32.22,57.34) 32.92,57.34 C156.1 ; v1(35.42,63.14) C69.1 ; v1(46.22,61.34) C146.1 ; C48.1 43.72,58.96 v1(43.75,58.93) ; C162.1 v1(37.02,63.14) ; v1(40.22,63.14) C150.1 ; C94.1 44.17,61.34 v1(43.02,61.34) ; C74.1 v1(43.02,58.14) ; v1(46.22,62.94) C130.1 ; v1(30.62,56.54) 31.32,56.54 C122.1 ; v1(26.62,63.14) C58.1
  vias: v2(42.8,22.54) v2(42.8,21.84) v2(42.8,21.08) v2(42.8,20.38) v2(43.5,21.84) v2(43.5,21.08) v2(57.66,71.12) v2(57.66,70.36) v2(57.66,68.07) v2(57.66,67.31)
